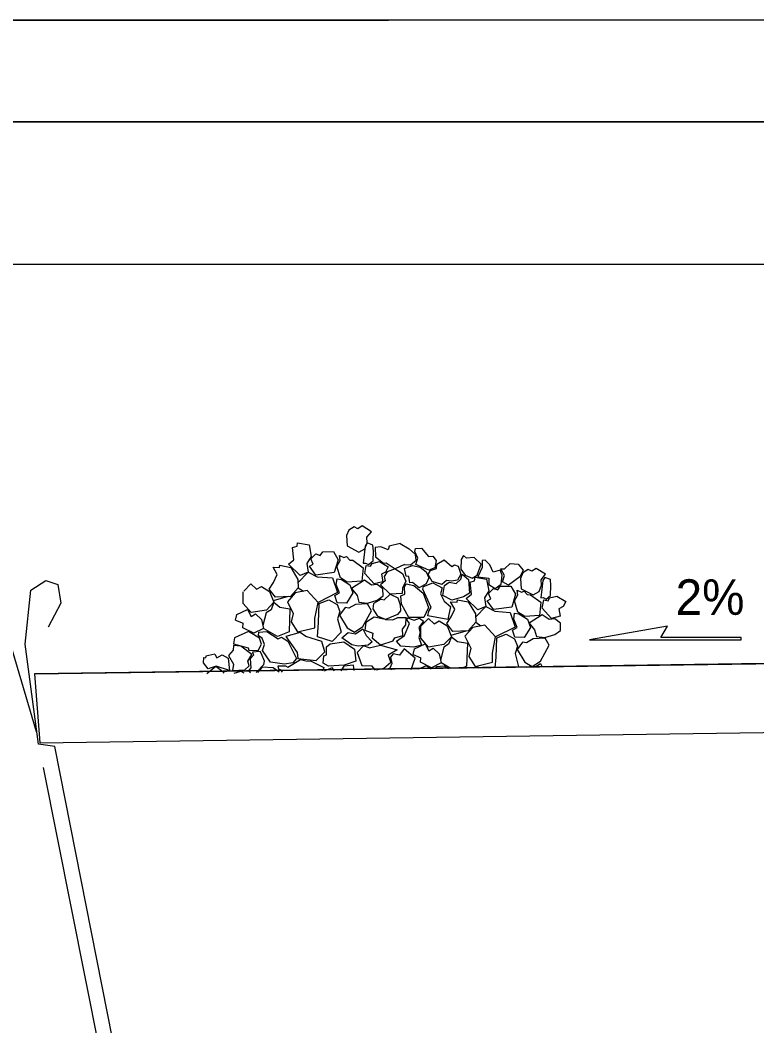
# Model space of a CAD drawing. Extents: x 99862 to 103151, y 100000 to 102076.
# Drawn here: x 100242.2 to 100572.9, y 101336.5 to 101788.4 of the extents above; entities that cross this region are included whole.
import ezdxf

# ---------------------------------------------------------------- set-up
doc = ezdxf.new("R2010")
doc.units = 0
for name, color, linetype in [('Level 11', 7, 'Continuous'), ('Level 14', 7, 'Continuous'), ('Level 17', 7, 'Continuous'), ('Level 20', 7, 'Continuous'), ('Level 4', 7, 'Continuous'), ('Level 8', 7, 'Continuous')]:
    doc.layers.add(name, color=color, linetype=linetype)

msp = doc.modelspace()

# ---------------------------------------------------------------- linework, layer by layer
at = {"layer": 'Level 11'}
msp.add_line((100439, 100516.37), (100252.72, 101452.61), dxfattribs=at)
for points in [[(100130.47, 101742.64), (100723.17, 101742.64), (100723.17, 101748.35), (100751.74, 101788.35), (100130.47, 101788.35), (100130.47, 101742.64)], [(100441.58, 100530.18), (100257.76, 101462), (100250.38, 101463.05), (100244.4, 101508.01), (100246.9, 101532.32), (100253.69, 101536.6), (100259.06, 101534.82), (100260.48, 101526.42), (100254.77, 101515.64)]]:
    msp.add_lwpolyline(points, dxfattribs=at)
at = {"layer": 'Level 14'}
msp.add_line((100713.57, 101678.64), (100022.86, 101678.64), dxfattribs=at)
at = {"layer": 'Level 17'}
msp.add_lwpolyline([(100607.17, 101479.67), (100618.96, 101499.9), (100248.69, 101494.66), (100250.94, 101463.69), (100607.13, 101468.71)], close=True, dxfattribs=at)
msp.add_lwpolyline([(100248.69, 101494.66), (100250.94, 101463.69), (100607.13, 101468.71)], dxfattribs=at)
at = {"layer": 'Level 4'}
for p, q in [((100364.44, 101551.37), (100366.5, 101551.98)), ((100365.03, 101545.91), (100364.44, 101551.37)), ((100366.5, 101551.98), (100366.73, 101553.54)), ((100366.73, 101553.54), (100371.85, 101552.67)), ((100371.85, 101552.67), (100372.83, 101547.4)), ((100404.12, 101551.78), (100401.54, 101551.4)), ((100401.54, 101551.4), (100401.64, 101547.25)), ((100407.42, 101550.4), (100404.12, 101551.78)), ((100407.88, 101552.03), (100407.42, 101550.4)), ((100412.78, 101553.18), (100407.88, 101552.03)), ((100412.78, 101553.18), (100416.76, 101550.81)), ((100372.83, 101547.4), (100370.93, 101544.31)), ((100401.64, 101547.25), (100405.29, 101544.47)), ((100419.62, 101548.29), (100416.76, 101550.81)), ((100419.97, 101545.77), (100419.62, 101548.29)), ((100357.62, 101539.28), (100355.7, 101542.53)), ((100355.7, 101542.53), (100358.58, 101542.44)), ((100358.58, 101542.44), (100358.78, 101543.47)), ((100358.78, 101543.47), (100363.61, 101542.47)), ((100362.66, 101543.98), (100365.03, 101545.91)), ((100367.94, 101538.87), (100362.66, 101543.98)), ((100363.61, 101542.47), (100366.83, 101537.09)), ((100370.93, 101544.31), (100371.53, 101540.37)), ((100405.29, 101544.47), (100406.43, 101544.56)), ((100406.43, 101544.56), (100410.57, 101541.79)), ((100414.7, 101543.73), (100410.57, 101541.79)), ((100414.7, 101543.73), (100417.41, 101543.66)), ((100417.41, 101543.66), (100419.97, 101545.77)), ((100355.96, 101535.73), (100357.62, 101539.28)), ((100371.53, 101540.37), (100366.89, 101535.58)), ((100371.53, 101540.37), (100367.94, 101538.87)), ((100371.53, 101540.37), (100375.56, 101538.26)), ((100375.56, 101538.26), (100382.43, 101537.79)), ((100382.43, 101537.79), (100384.62, 101531.17)), ((100407, 101540.44), (100405.51, 101538.46)), ((100405.51, 101538.46), (100406.08, 101536.47)), ((100410.57, 101541.79), (100407, 101540.44)), ((100410.57, 101541.79), (100413.79, 101539.77)), ((100413.79, 101539.77), (100415.32, 101536.27)), ((100440, 101537.22), (100440.64, 101539.43)), ((100440.64, 101539.43), (100443.5, 101537.08)), ((100446.2, 101536.48), (100446.44, 101538.04)), ((100446.44, 101538.04), (100451.56, 101537.18)), ((100342.53, 101531.89), (100345.71, 101535.07)), ((100345.71, 101535.07), (100348.28, 101532.69)), ((100348.28, 101532.69), (100350.52, 101533.93)), ((100350.52, 101533.93), (100354.16, 101531.74)), ((100353.95, 101532.79), (100355.96, 101535.73)), ((100367, 101533.33), (100363.56, 101529.45)), ((100366.83, 101537.09), (100367, 101533.33)), ((100367, 101533.33), (100369.34, 101531.75)), ((100406.08, 101536.47), (100403.94, 101534.62)), ((100403.94, 101534.62), (100408.35, 101530.4)), ((100413.76, 101533.24), (100413.71, 101530.84)), ((100415.32, 101536.27), (100413.76, 101533.24)), ((100431.96, 101529.83), (100432.64, 101534.38)), ((100432.64, 101534.38), (100434.71, 101535.85)), ((100434.71, 101535.85), (100437.91, 101535.29)), ((100437.91, 101535.29), (100440, 101537.22)), ((100443.5, 101537.08), (100443.9, 101530.99)), ((100444.15, 101535.88), (100446.2, 101536.48)), ((100444.74, 101530.42), (100444.15, 101535.88)), ((100451.56, 101537.18), (100452.54, 101531.91)), ((100342.35, 101526.23), (100342.29, 101531.52)), ((100356.76, 101529.17), (100353.95, 101532.79)), ((100354.16, 101531.74), (100356.03, 101526.84)), ((100362.49, 101529.41), (100355.8, 101527.47)), ((100363.56, 101529.45), (100356.76, 101529.17)), ((100365.63, 101531.04), (100362.16, 101527.04)), ((100370.99, 101532.07), (100365.63, 101531.04)), ((100375.91, 101526.76), (100370.99, 101532.07)), ((100384.62, 101531.17), (100375.91, 101526.76)), ((100405.54, 101527.94), (100408.35, 101530.4)), ((100413.71, 101530.84), (100408.35, 101530.4)), ((100408.35, 101530.4), (100411.67, 101528.84)), ((100411.67, 101528.84), (100412.71, 101525.69)), ((100435.98, 101527.85), (100431.96, 101529.83)), ((100441.23, 101529.31), (100435.98, 101527.85)), ((100443.9, 101530.99), (100441.23, 101529.31)), ((100442.37, 101528.48), (100444.74, 101530.42)), ((100452.54, 101531.91), (100450.63, 101528.82)), ((100450.63, 101528.82), (100451.24, 101524.88)), ((100345.83, 101522.21), (100342.35, 101526.23)), ((100356.03, 101526.84), (100352.72, 101523.28)), ((100356.03, 101526.84), (100354.82, 101523.47)), ((100356.03, 101526.84), (100358.77, 101524.64)), ((100358.77, 101524.64), (100363.24, 101523.91)), ((100362.16, 101527.04), (100364.72, 101521.75)), ((100374.5, 101519.52), (100375.91, 101526.76)), ((100400.84, 101526.33), (100400.5, 101523.81)), ((100404.2, 101528.2), (100400.84, 101526.33)), ((100404.2, 101528.2), (100405.54, 101527.94)), ((100412.71, 101525.69), (100412.87, 101522.99)), ((100437.33, 101523.79), (100435.41, 101527.04)), ((100435.41, 101527.04), (100438.29, 101526.95)), ((100438.29, 101526.95), (100438.49, 101527.97)), ((100438.49, 101527.97), (100443.32, 101526.98)), ((100447.65, 101523.38), (100442.37, 101528.48)), ((100443.32, 101526.98), (100446.54, 101521.6)), ((100451.24, 101524.88), (100446.6, 101520.09)), ((100451.24, 101524.88), (100447.65, 101523.38)), ((100451.24, 101524.88), (100455.27, 101522.76)), ((100338.84, 101518.83), (100339.47, 101521.38)), ((100339.47, 101521.38), (100344.25, 101523.59)), ((100344.25, 101523.59), (100345.91, 101520.47)), ((100352.72, 101523.28), (100345.83, 101522.21)), ((100345.91, 101520.47), (100347.8, 101521.7)), ((100347.8, 101521.7), (100350.53, 101519.1)), ((100352.64, 101522.16), (100351.18, 101516.34)), ((100354.82, 101523.47), (100352.64, 101522.16)), ((100363.24, 101523.91), (100362.89, 101513.62)), ((100364.72, 101521.75), (100363.89, 101518)), ((100401.08, 101520.1), (100397.35, 101517.73)), ((100400.5, 101523.81), (100402.6, 101520.64)), ((100406.14, 101519.02), (100401.08, 101520.1)), ((100406.14, 101519.02), (100402.6, 101520.64)), ((100411.6, 101521.37), (100406.14, 101519.02)), ((100409.4, 101518.95), (100411.7, 101520.01)), ((100412.87, 101522.99), (100411.6, 101521.37)), ((100411.7, 101520.01), (100415.44, 101520.03)), ((100415.26, 101516.68), (100415.44, 101520.03)), ((100433.66, 101517.3), (100435.67, 101520.24)), ((100435.67, 101520.24), (100437.33, 101523.79)), ((100446.54, 101521.6), (100446.7, 101517.83)), ((100455.27, 101522.76), (100462.14, 101522.3)), ((100462.14, 101522.3), (100464.33, 101515.67)), ((100338.84, 101518.83), (100342.35, 101517.41)), ((100342.17, 101515.38), (100342.35, 101517.41)), ((100347.12, 101512.88), (100342.17, 101515.38)), ((100350.53, 101519.1), (100351.47, 101515.11)), ((100363.89, 101518), (100366.72, 101513.53)), ((100366.72, 101513.53), (100374.49, 101515.39)), ((100374.49, 101515.39), (100374.5, 101519.52)), ((100397.35, 101517.73), (100396.9, 101514.28)), ((100406.14, 101519.02), (100409.4, 101518.95)), ((100413.87, 101514.76), (100415.26, 101516.68)), ((100422, 101516.16), (100425.42, 101519.57)), ((100422.06, 101510.74), (100422, 101516.16)), ((100425.42, 101519.57), (100427.99, 101517.19)), ((100427.99, 101517.19), (100430.23, 101518.44)), ((100430.23, 101518.44), (100433.87, 101516.25)), ((100436.47, 101513.68), (100433.66, 101517.3)), ((100433.87, 101516.25), (100435.74, 101511.35)), ((100445.34, 101515.55), (100441.86, 101511.54)), ((100446.7, 101517.83), (100443.27, 101513.95)), ((100450.7, 101516.57), (100445.34, 101515.55)), ((100446.7, 101517.83), (100449.04, 101516.26)), ((100455.61, 101511.27), (100450.7, 101516.57)), ((100464.33, 101515.67), (100455.61, 101511.27)), ((100338.34, 101510.9), (100338.02, 101508.22)), ((100344.67, 101513.75), (100338.34, 101510.9)), ((100349.58, 101510.66), (100344.67, 101513.75)), ((100351.47, 101515.11), (100347.12, 101512.88)), ((100350.53, 101508.06), (100349.58, 101510.66)), ((100357.72, 101511.43), (100351.47, 101515.11)), ((100362.89, 101513.62), (100357.72, 101511.43)), ((100367.9, 101513.3), (100361.5, 101511.49)), ((100361.5, 101511.49), (100366.48, 101504.22)), ((100370.45, 101511.38), (100367.9, 101513.3)), ((100377.66, 101509.23), (100370.45, 101511.38)), ((100396.9, 101514.28), (100400.46, 101513)), ((100400.46, 101513), (100400.25, 101510.67)), ((100403.93, 101507.63), (100400.25, 101510.67)), ((100409.4, 101509.38), (100410.39, 101510.83)), ((100410.39, 101510.83), (100414.03, 101511.93)), ((100414.03, 101511.93), (100413.87, 101514.76)), ((100425.54, 101506.71), (100422.06, 101510.74)), ((100435.74, 101511.35), (100432.43, 101507.79)), ((100435.74, 101511.35), (100434.53, 101507.98)), ((100442.19, 101513.91), (100435.51, 101511.97)), ((100435.74, 101511.35), (100438.48, 101509.15)), ((100443.27, 101513.95), (100436.47, 101513.68)), ((100441.86, 101511.54), (100444.43, 101506.26)), ((100454.21, 101504.03), (100455.61, 101511.27)), ((100337.94, 101507.43), (100337.8, 101505.32)), ((100341.3, 101507.05), (100337.94, 101507.43)), ((100338.02, 101508.22), (100344.56, 101506.42)), ((100346.18, 101503.43), (100341.3, 101507.05)), ((100344.56, 101506.42), (100344.83, 101505.3)), ((100348.98, 101505.09), (100350.53, 101508.06)), ((100378.91, 101504.62), (100377.66, 101509.23)), ((100396.29, 101507.19), (100393.43, 101504.21)), ((100398.87, 101506.39), (100396.29, 101507.19)), ((100398.87, 101506.39), (100403.93, 101507.63)), ((100409.4, 101509.38), (100403.93, 101507.63)), ((100403.93, 101507.63), (100411.38, 101505.44)), ((100419.17, 101505.88), (100423.95, 101508.1)), ((100423.95, 101508.1), (100425.62, 101504.97)), ((100432.43, 101507.79), (100425.54, 101506.71)), ((100425.62, 101504.97), (100427.51, 101506.2)), ((100427.51, 101506.2), (100430.24, 101503.6)), ((100432.35, 101506.67), (100430.89, 101500.84)), ((100434.53, 101507.98), (100432.35, 101506.67)), ((100438.48, 101509.15), (100442.95, 101508.41)), ((100442.95, 101508.41), (100442.6, 101498.13)), ((100444.43, 101506.26), (100443.59, 101502.51)), ((100325.46, 101502.66), (100325.36, 101501.86)), ((100329.58, 101503.54), (100325.46, 101502.66)), ((100329.58, 101503.54), (100330.4, 101501.89)), ((100330.4, 101501.89), (100332.85, 101503.21)), ((100332.85, 101503.21), (100335.53, 101501.76)), ((100335.53, 101501.76), (100336.17, 101496.22)), ((100337.8, 101505.32), (100335.75, 101502.92)), ((100335.75, 101502.92), (100337.96, 101499.02)), ((100344.4, 101500.31), (100346.18, 101503.43)), ((100344.83, 101505.3), (100348.98, 101505.09)), ((100366.48, 101504.22), (100366.87, 101501.63)), ((100366.87, 101501.63), (100375, 101500.71)), ((100375, 101500.71), (100378.91, 101504.62)), ((100393.43, 101504.21), (100395.58, 101498.41)), ((100411.38, 101505.44), (100407.33, 101503.02)), ((100407.33, 101503.02), (100408.62, 101499.7)), ((100409.58, 101503.6), (100408.42, 101502.15)), ((100408.42, 101502.15), (100409.04, 101499.36)), ((100412.51, 101503.03), (100409.58, 101503.6)), ((100414.59, 101505.96), (100412.51, 101503.03)), ((100419.49, 101501.73), (100414.59, 101505.96)), ((100417.73, 101496.67), (100419.49, 101501.73)), ((100418.55, 101503.33), (100419.17, 101505.88)), ((100418.55, 101503.33), (100422.06, 101501.92)), ((100421.87, 101499.89), (100422.06, 101501.92)), ((100430.24, 101503.6), (100431.18, 101499.62)), ((100443.59, 101502.51), (100446.42, 101498.03)), ((100454.19, 101499.89), (100454.21, 101504.03)), ((100248.69, 101494.66), (100618.96, 101499.9)), ((100326.54, 101496.96), (100324.44, 101499.58)), ((100325.91, 101494.8), (100330, 101498.14)), ((100330.22, 101498.18), (100326.54, 101496.96)), ((100330, 101498.14), (100333.1, 101495.67)), ((100336.17, 101496.22), (100330.22, 101498.18)), ((100337.96, 101499.02), (100337.47, 101496.17)), ((100342.97, 101496.51), (100345.05, 101498.31)), ((100345.05, 101498.31), (100344.4, 101500.31)), ((100350.84, 101497.66), (100348.76, 101495.27)), ((100355.76, 101497.38), (100350.84, 101497.66)), ((100358.42, 101495.46), (100355.76, 101497.38)), ((100382.2, 101497.35), (100378.91, 101496.03)), ((100383.25, 101495.97), (100382.2, 101497.35)), ((100387.5, 101498.06), (100386.15, 101496.03)), ((100391.87, 101498.63), (100387.5, 101498.06)), ((100392.18, 101496.15), (100391.87, 101498.63)), ((100395.58, 101498.41), (100400.04, 101498.29)), ((100401.63, 101496.34), (100400.04, 101498.29)), ((100405.37, 101497.12), (100402.17, 101496.35)), ((100408.62, 101499.7), (100405.37, 101497.12)), ((100409.04, 101499.36), (100408.08, 101497.27)), ((100408.08, 101497.27), (100408.92, 101496.49)), ((100424.38, 101498.25), (100421, 101496.73)), ((100426.82, 101497.39), (100421.87, 101499.89)), ((100426.61, 101496.85), (100424.38, 101498.25)), ((100431.18, 101499.62), (100426.82, 101497.39)), ((100435.56, 101497.03), (100431.18, 101499.62)), ((100442.6, 101498.13), (100440.24, 101497.12)), ((100447.61, 101497.8), (100445.58, 101497.23)), ((100446.42, 101498.03), (100454.19, 101499.89)), ((100448.29, 101497.29), (100447.61, 101497.8)), ((100333.1, 101495.67), (100333.54, 101494.96)), ((100337.47, 101496.17), (100342.97, 101496.51)), ((100338.27, 101495.05), (100341.28, 101495.95)), ((100341.28, 101495.95), (100342.62, 101495.14)), ((100378.91, 101496.03), (100378.84, 101495.88))]:
    msp.add_line(p, q, dxfattribs=at)
for points in [[(100249.53, 101468.64), (100227.17, 101543.68), (100187.59, 101600.97), (100162.28, 101658.82), (100137.98, 101742.64)], [(100473.77, 101542.06), (100471.93, 101540.74), (100470.27, 101541.57), (100467.77, 101540), (100466.83, 101537.52), (100467.14, 101532.89), (100472.54, 101530.22), (100475.11, 101531.7), (100476.19, 101534.52), (100475.99, 101536.92), (100477.99, 101539.47), (100473.85, 101542.03)], [(100565.83, 101510.95), (100529.76, 101510.93), (100532.75, 101516.12), (100497.75, 101509.93), (100565.83, 101509.93)], [(100455.47, 101497.43), (100455.87, 101502.21), (100456.17, 101510.78), (100460.4, 101512.49), (100464.13, 101510.34), (100465.42, 101507.12), (100464.32, 101503.84), (100465.91, 101497.87), (100465.69, 101497.64)], [(100565.83, 101509.93), (100565.83, 101510.95)], [(100324.44, 101499.58), (100324.58, 101501.96), (100325.36, 101501.86)], [(100348.16, 101495.26), (100351.54, 101498.88), (100351.82, 101500.33), (100350.51, 101503.61), (100349.96, 101504.7), (100346.47, 101504.39), (100347, 101503.09), (100345.5, 101501.42), (100345.72, 101497.37), (100344.75, 101495.97), (100345.6, 101495.2)], [(100359.88, 101495.49), (100359.31, 101496.39), (100358.3, 101496.81), (100358.05, 101498.29), (100361.3, 101498.26), (100362.34, 101497.61), (100368.08, 101501.1), (100370.46, 101500.49), (100372.78, 101500.41), (100378.43, 101497.5), (100377.9, 101495.86)], [(100428.95, 101496.9), (100429.1, 101497.92), (100432.57, 101498.22), (100434.49, 101497.01)], [(100469.04, 101497.71), (100469.12, 101497.78), (100469.45, 101497.72)], [(100473.36, 101497.8), (100475.79, 101499.38), (100476.52, 101497.86)]]:
    msp.add_lwpolyline(points, dxfattribs=at)
for points in [[(100399.87, 101558.53), (100395.7, 101561.19), (100393.83, 101559.89), (100392.18, 101560.75), (100389.65, 101559.23), (100388.67, 101556.77), (100388.9, 101552.13), (100394.26, 101549.37), (100396.85, 101550.81), (100397.98, 101553.6), (100397.82, 101556.01)], [(100400.76, 101549.78), (100400.55, 101552.55), (100397.99, 101553.49), (100397.1, 101552.04), (100396.14, 101544.34), (100397.22, 101544.42), (100398.62, 101543.78), (100400.59, 101545.38)], [(100372.11, 101543.04), (100373.72, 101543.9), (100372.66, 101546.31), (100374.93, 101548.53), (100376.92, 101547.85), (100378.01, 101549.55), (100382.8, 101549.58), (100384.9, 101545.93), (100383.17, 101540.14), (100374.97, 101539.01)], [(100384.32, 101542.95), (100385.83, 101545.6), (100385.57, 101547.78), (100387.46, 101546.91), (100388.74, 101547.32), (100390.12, 101545.8), (100391.55, 101545.74), (100396.14, 101542.34), (100395.58, 101536.34), (100389.04, 101535.91), (100385.92, 101537.84)], [(100419.41, 101549.6), (100419.61, 101551.05), (100422.32, 101551.18), (100425.49, 101547.37), (100427.38, 101547.6), (100428.99, 101545.66), (100428.33, 101542.29), (100425.6, 101541.26), (100419.82, 101543.87), (100420.67, 101546.67)], [(100445.92, 101546.89), (100442.6, 101546.58), (100441.23, 101547.8), (100440.13, 101546.03), (100440.04, 101541.7), (100441.95, 101538.96), (100445.13, 101537.68), (100447.28, 101539.04), (100449.16, 101543.98)], [(100396.83, 101539.71), (100397.48, 101543.41), (100399.45, 101543.03), (100400.16, 101544.3), (100403.43, 101545.13), (100407.37, 101542.74), (100406.16, 101540.4), (100404.31, 101539.44), (100404.94, 101536.07), (100401.02, 101535.06)], [(100415.51, 101538.61), (100414.78, 101541.95), (100418.36, 101543.41), (100421.71, 101542.53), (100424.46, 101540.51), (100425.69, 101537.74), (100424.42, 101535.16), (100421.23, 101533.34), (100418.33, 101535.76), (100417.16, 101535.62), (100416.62, 101538.39)], [(100425.39, 101539.37), (100426.41, 101541.03), (100429.14, 101542.06), (100429.27, 101543.96), (100432.56, 101545.85), (100435.96, 101542.88), (100437.1, 101543.63), (100438.75, 101543.01), (100440.05, 101539.49), (100438.52, 101536.73), (100435.76, 101536.3), (100433.6, 101536.65), (100431.41, 101534.86), (100427.15, 101536.2)], [(100452.98, 101543.67), (100450.94, 101545.69), (100449.62, 101545.58), (100449.53, 101542.43), (100447.6, 101538.31), (100452.5, 101537.73), (100452.55, 101534.84), (100455.46, 101533.02), (100458.11, 101534.94), (100458.6, 101538.98), (100457.6, 101541.3), (100454.45, 101540.29)], [(100458.01, 101541.81), (100459.6, 101541.8), (100462.2, 101544.25), (100465.8, 101543.98), (100467.94, 101541.29), (100466.44, 101538.26), (100461.44, 101534.44), (100458.72, 101536.07), (100459.65, 101538.91)], [(100480.47, 101534.29), (100480.26, 101537.06), (100477.7, 101538), (100476.81, 101536.55), (100475.85, 101528.84), (100476.93, 101528.93), (100478.33, 101528.29), (100480.3, 101529.89)], [(100384.02, 101534.76), (100384.45, 101537.4), (100386.36, 101537.1), (100390.16, 101534.67), (100391.57, 101531.01), (100388.71, 101526.47), (100384.48, 101526.63), (100383.51, 101529.84), (100385.58, 101531.06)], [(100405.01, 101532.89), (100402.49, 101534.85), (100399.93, 101534.55), (100396.78, 101536.71), (100390.96, 101532.97), (100393.4, 101529.91), (100394.28, 101526.94), (100398.06, 101526.43), (100402.5, 101527.84), (100405.08, 101529.71)], [(100414.71, 101533.66), (100415.51, 101535.06), (100418.9, 101534.4), (100423.06, 101530.92), (100425.42, 101524.51), (100423.32, 101520.02), (100416.58, 101520.06), (100413.29, 101525.98), (100413.09, 101529.73), (100414.85, 101530.51)], [(100422.95, 101532.73), (100423.17, 101533.88), (100427.48, 101535.56), (100431.64, 101533.28), (100430.81, 101530.6), (100432.47, 101527.31), (100435.39, 101524.96), (100434.1, 101519.11), (100425.21, 101520.69), (100425.63, 101522.84), (100426.73, 101524.55)], [(100451.82, 101527.55), (100453.43, 101528.4), (100452.37, 101530.82), (100454.63, 101533.04), (100456.63, 101532.35), (100457.72, 101534.06), (100462.51, 101534.08), (100464.61, 101530.44), (100462.88, 101524.65), (100454.67, 101523.52)], [(100464.03, 101527.45), (100465.54, 101530.1), (100465.28, 101532.29), (100467.16, 101531.42), (100468.45, 101531.83), (100469.83, 101530.31), (100471.26, 101530.24), (100475.85, 101526.84), (100475.28, 101520.84), (100468.75, 101520.41), (100465.62, 101522.34)], [(100476.54, 101524.22), (100477.19, 101527.92), (100479.16, 101527.54), (100479.87, 101528.8), (100483.14, 101529.63), (100487.08, 101527.25), (100485.87, 101524.91), (100484.02, 101523.95), (100484.65, 101520.57), (100480.73, 101519.56)], [(100376.46, 101526.28), (100380.69, 101527.98), (100384.42, 101525.84), (100385.71, 101522.61), (100384.61, 101519.34), (100386.21, 101513.37), (100382.18, 101509.18), (100375.62, 101511.34), (100376.17, 101517.71)], [(100399.9, 101523.03), (100398.08, 101526.19), (100392.71, 101525.89), (100389.78, 101524.11), (100388.02, 101524.45), (100385.55, 101521.09), (100389, 101515.41), (100392.26, 101513.45), (100396.02, 101515.93)], [(100415.96, 101518.73), (100416.11, 101519.83), (100419.02, 101518.81), (100421.43, 101519.63), (100423.29, 101518.35), (100421.18, 101515.53), (100421.68, 101513.31), (100421.18, 101511.07), (100422.29, 101507.61), (100418.83, 101506.62), (100413.1, 101507.14), (100411.1, 101509.33), (100414.78, 101511.87), (100417, 101517.24)], [(100463.73, 101519.26), (100464.16, 101521.91), (100466.07, 101521.61), (100469.87, 101519.18), (100471.28, 101515.51), (100468.41, 101510.98), (100464.19, 101511.14), (100463.22, 101514.35), (100465.29, 101515.57)], [(100484.72, 101517.39), (100482.2, 101519.36), (100479.64, 101519.05), (100476.49, 101521.21), (100470.67, 101517.48), (100473.11, 101514.41), (100473.99, 101511.44), (100477.76, 101510.93), (100482.21, 101512.35), (100484.78, 101514.21)], [(100349.15, 101511.8), (100349.39, 101513.41), (100352.87, 101513.71), (100358, 101510.46), (100359.53, 101511.14), (100362.36, 101509.31), (100366.16, 101501.62), (100364.54, 101499.68), (100360.84, 101499.04), (100354.62, 101499.87), (100351.04, 101505.09), (100351.82, 101507.88), (100350.81, 101510.72)], [(100389.41, 101513.28), (100392.66, 101512.64), (100396.08, 101514.87), (100397.5, 101511.92), (100400.24, 101509.01), (100398.42, 101507.58), (100393.97, 101507.18), (100391.02, 101507.75), (100386.58, 101510.92)], [(100479.61, 101507.54), (100477.79, 101510.69), (100472.41, 101510.4), (100469.49, 101508.62), (100467.73, 101508.96), (100465.25, 101505.6), (100468.71, 101499.92), (100471.97, 101497.96), (100475.72, 101500.43)], [(100379.71, 101506.75), (100381.31, 101508.22), (100387.43, 101509.04), (100392.31, 101505.72), (100392.81, 101500.41), (100387.63, 101498.59), (100380.57, 101498.18), (100378.22, 101499.46), (100378.48, 101502.83), (100379.63, 101503.19)]]:
    msp.add_lwpolyline(points, close=True, dxfattribs=at)
at = {"layer": 'Level 8'}
for p, q in [((100751.74, 101788.35), (100130.44, 101788)), ((100723.17, 101742.64), (100130.47, 101742.64))]:
    msp.add_line(p, q, dxfattribs=at)

# ---------------------------------------------------------------- texts
at = {"layer": 'Level 20'}
msp.add_text('2%', height=16, rotation=0.018, dxfattribs=at).set_placement((100536.42, 101521.14))

doc.saveas('drawing.dxf')
